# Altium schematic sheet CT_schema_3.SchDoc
size 208 x 169 mm
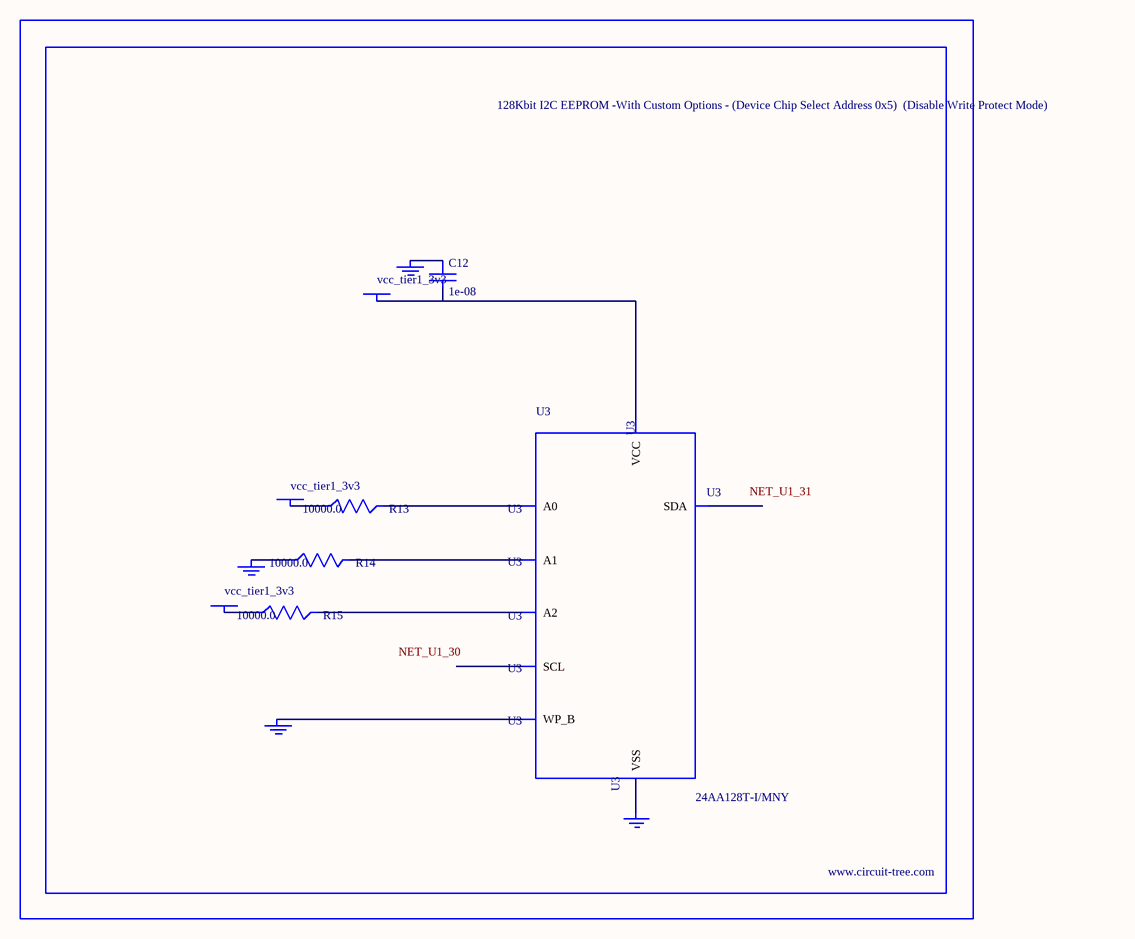
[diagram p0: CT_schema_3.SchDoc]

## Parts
BORDER2  (no value)
C12  1e-08  [C0402]
GND_INSTANCE_2_0  (no value)
GND_INSTANCE_2_1  (no value)
GND_INSTANCE_2_2  (no value)
GND_INSTANCE_2_3  (no value)
POWER_INSTANCE_2_0  vcc_tier1_3v3
POWER_INSTANCE_2_1  vcc_tier1_3v3
POWER_INSTANCE_2_2  vcc_tier1_3v3
R13  10000.0  [R0603]
R14  10000.0  [R0603]
R15  10000.0  [R0603]
U3  24AA128T-I/MNY  [TDFN-8/6MM]

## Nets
NetC12_1: C12.1 GND_INSTANCE_2_2.0(GND)
NetC12_2: C12.2 POWER_INSTANCE_2_2.0(PWR) U3.8(VCC)
NetGND_INSTANCE_2_0_0: GND_INSTANCE_2_0.0(GND) R14.1
NetGND_INSTANCE_2_1_0: GND_INSTANCE_2_1.0(GND) U3.7(WP_B)
NetGND_INSTANCE_2_3_0: GND_INSTANCE_2_3.0(GND) U3.4(VSS)
NetPOWER_INSTANCE_2_0_0: POWER_INSTANCE_2_0.0(PWR) R13.1
NetPOWER_INSTANCE_2_1_0: POWER_INSTANCE_2_1.0(PWR) R15.1
NetR13_2: R13.2 U3.1(A0)
NetR14_2: R14.2 U3.2(A1)
NetR15_2: R15.2 U3.3(A2)

Not connected (* = marked no-connect by the designer): U3 5(SDA) 6(SCL)

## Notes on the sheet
- Labels drawn without touching a wire or pin: NET_U1_30, NET_U1_31

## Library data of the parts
BORDER2 = BORDER_PAGE2
C12 = C0402C103K3RAC
GND_INSTANCE_2_0-GND_INSTANCE_2_3 = GND
POWER_INSTANCE_2_0-POWER_INSTANCE_2_2 = PWR
R13-R15 = RC0603JR-0710KL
